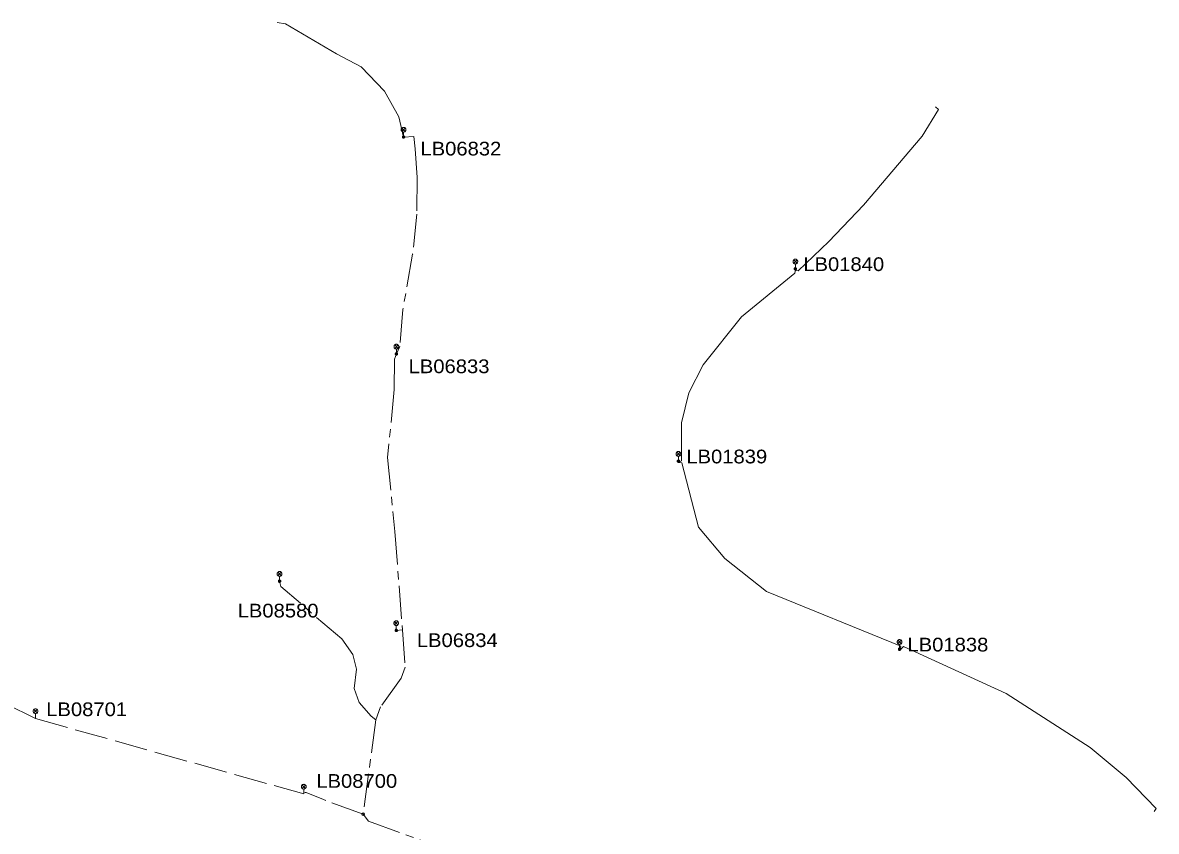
# Model space of a CAD drawing. Extents: x -686371 to -686009, y -974088 to -973838.
# Drawn here: x -686188.2 to -686009.3, y -973965.5 to -973837.8 of the extents above; entities that cross this region are included whole.
import ezdxf

# ---------------------------------------------------------------- set-up
doc = ezdxf.new("R2010")
doc.units = 0
doc.header["$LTSCALE"] = 0.87
doc.header["$PDMODE"] = 32
doc.header["$PDSIZE"] = 0.435
doc.linetypes.add('LONG_DASH_SHORT_DASH', pattern=[9.9, 6, -1.2, 1.5, -1.2])
doc.linetypes.add('LONG_DASHED', pattern=[7.5, 6, -1.5])
doc.layers.add('1', color=7, linetype='Continuous', lineweight=13)

msp = doc.modelspace()

# ---------------------------------------------------------------- linework, layer by layer
at = {"layer": '1'}
for p, q in [((-686128.345, -973854.435), (-686127.815, -973854.965)), ((-686128.345, -973854.965), (-686127.815, -973854.435)), ((-686128.08, -973855.85), (-686128.08, -973855.075)), ((-686066.505, -973875.245), (-686065.975, -973875.775)), ((-686066.505, -973875.775), (-686065.975, -973875.245)), ((-686066.24, -973876.66), (-686066.24, -973875.885)), ((-686129.475, -973888.685), (-686128.945, -973889.215)), ((-686129.475, -973889.215), (-686128.945, -973888.685)), ((-686129.21, -973890.1), (-686129.21, -973889.325)), ((-686084.965, -973905.615), (-686084.435, -973906.145)), ((-686084.965, -973906.145), (-686084.435, -973905.615)), ((-686084.7, -973907.03), (-686084.7, -973906.255)), ((-686147.915, -973924.565), (-686147.385, -973925.095)), ((-686147.915, -973925.095), (-686147.385, -973924.565)), ((-686147.65, -973925.98), (-686147.65, -973925.205)), ((-686129.495, -973932.345), (-686128.965, -973932.875)), ((-686129.495, -973932.875), (-686128.965, -973932.345)), ((-686129.23, -973933.76), (-686129.23, -973932.985)), ((-686050.065, -973935.315), (-686049.535, -973935.845)), ((-686050.065, -973935.845), (-686049.535, -973935.315)), ((-686049.8, -973936.73), (-686049.8, -973935.955)), ((-686186.425, -973946.245), (-686185.895, -973946.775)), ((-686186.425, -973946.775), (-686185.895, -973946.245)), ((-686186.16, -973947.66), (-686186.16, -973946.885)), ((-686144.085, -973958.165), (-686143.555, -973958.695)), ((-686144.085, -973958.695), (-686143.555, -973958.165)), ((-686143.82, -973959.58), (-686143.82, -973958.805))]:
    msp.add_line(p, q, dxfattribs=at)
at = {"layer": '1', "linetype": 'LONG_DASH_SHORT_DASH'}
for p, q in [((-686129.45, -973918.15), (-686128.26, -973933.66)), ((-686147.47, -973926.8), (-686147.65, -973925.98)), ((-686128.26, -973933.66), (-686129.23, -973933.76)), ((-686132.43, -973947.89), (-686134.47, -973962.76))]:
    msp.add_line(p, q, dxfattribs=at)
at = {"layer": '1', "linetype": 'LONG_DASHED'}
for q in [(-686211.97, -973935.089), (-686143.82, -973959.58)]:
    msp.add_line((-686186.16, -973947.66), q, dxfattribs=at)
at = {"layer": '1'}
for points in [[(-686148, -973837.79), (-686146.706, -973837.955), (-686138.636, -973842.736), (-686134.764, -973844.768), (-686131.105, -973848.588), (-686128.833, -973852.64), (-686128.08, -973855.85)], [(-686066.24, -973876.85), (-686065.828, -973876.979), (-686060.945, -973872.351), (-686055.499, -973866.609), (-686046.253, -973855.711), (-686043.665, -973851.493), (-686044.13, -973851.1)], [(-686084.7, -973907.22), (-686084.224, -973906.978), (-686084.224, -973901.001), (-686083.04, -973896.221), (-686080.791, -973891.806), (-686074.769, -973884.239), (-686066.31, -973877.367), (-686066.24, -973876.85)], [(-686049.8, -973936.92), (-686049.591, -973936.237), (-686070.819, -973927.615), (-686077.37, -973922.407), (-686081.535, -973917.438), (-686084.168, -973907.28), (-686084.7, -973907.22)], [(-686009.61, -973962.37), (-686009.281, -973961.862), (-686014.053, -973956.992), (-686019.73, -973952.267), (-686032.954, -973943.714), (-686049.205, -973936.292), (-686049.8, -973936.92)]]:
    msp.add_lwpolyline(points, dxfattribs=at)
for points in [[(-686127.705, -973854.7), (-686127.711, -973854.635), (-686127.728, -973854.572), (-686127.755, -973854.513), (-686127.793, -973854.459), (-686127.839, -973854.413), (-686127.892, -973854.375), (-686127.952, -973854.348), (-686128.015, -973854.331), (-686128.08, -973854.325), (-686128.145, -973854.331), (-686128.208, -973854.348), (-686128.268, -973854.375), (-686128.321, -973854.413), (-686128.367, -973854.459), (-686128.405, -973854.513), (-686128.432, -973854.572), (-686128.449, -973854.635), (-686128.455, -973854.7), (-686128.449, -973854.765), (-686128.432, -973854.828), (-686128.405, -973854.888), (-686128.367, -973854.941), (-686128.321, -973854.987), (-686128.268, -973855.025), (-686128.208, -973855.052), (-686128.145, -973855.069), (-686128.08, -973855.075), (-686128.015, -973855.069), (-686127.952, -973855.052), (-686127.892, -973855.025), (-686127.839, -973854.987), (-686127.793, -973854.941), (-686127.755, -973854.888), (-686127.728, -973854.828), (-686127.711, -973854.765)], [(-686127.89, -973855.85), (-686127.893, -973855.817), (-686127.901, -973855.785), (-686127.915, -973855.755), (-686127.934, -973855.728), (-686127.958, -973855.704), (-686127.985, -973855.685), (-686128.015, -973855.671), (-686128.047, -973855.663), (-686128.08, -973855.66), (-686128.113, -973855.663), (-686128.145, -973855.671), (-686128.175, -973855.685), (-686128.202, -973855.704), (-686128.226, -973855.728), (-686128.245, -973855.755), (-686128.259, -973855.785), (-686128.267, -973855.817), (-686128.27, -973855.85), (-686128.267, -973855.883), (-686128.259, -973855.915), (-686128.245, -973855.945), (-686128.226, -973855.972), (-686128.202, -973855.996), (-686128.175, -973856.015), (-686128.145, -973856.029), (-686128.113, -973856.037), (-686128.08, -973856.04), (-686128.047, -973856.037), (-686128.015, -973856.029), (-686127.985, -973856.015), (-686127.958, -973855.996), (-686127.934, -973855.972), (-686127.915, -973855.945), (-686127.901, -973855.915), (-686127.893, -973855.883)], [(-686128.03, -973855.85), (-686128.031, -973855.841), (-686128.033, -973855.833), (-686128.037, -973855.825), (-686128.042, -973855.818), (-686128.048, -973855.812), (-686128.055, -973855.807), (-686128.063, -973855.803), (-686128.071, -973855.801), (-686128.08, -973855.8), (-686128.089, -973855.801), (-686128.097, -973855.803), (-686128.105, -973855.807), (-686128.112, -973855.812), (-686128.118, -973855.818), (-686128.123, -973855.825), (-686128.127, -973855.833), (-686128.129, -973855.841), (-686128.13, -973855.85), (-686128.129, -973855.859), (-686128.127, -973855.867), (-686128.123, -973855.875), (-686128.118, -973855.882), (-686128.112, -973855.888), (-686128.105, -973855.893), (-686128.097, -973855.897), (-686128.089, -973855.899), (-686128.08, -973855.9), (-686128.071, -973855.899), (-686128.063, -973855.897), (-686128.055, -973855.893), (-686128.048, -973855.888), (-686128.042, -973855.882), (-686128.037, -973855.875), (-686128.033, -973855.867), (-686128.031, -973855.859)], [(-686065.865, -973875.51), (-686065.871, -973875.445), (-686065.888, -973875.382), (-686065.915, -973875.322), (-686065.953, -973875.269), (-686065.999, -973875.223), (-686066.052, -973875.185), (-686066.112, -973875.158), (-686066.175, -973875.141), (-686066.24, -973875.135), (-686066.305, -973875.141), (-686066.368, -973875.158), (-686066.428, -973875.185), (-686066.481, -973875.223), (-686066.527, -973875.269), (-686066.565, -973875.322), (-686066.592, -973875.382), (-686066.609, -973875.445), (-686066.615, -973875.51), (-686066.609, -973875.575), (-686066.592, -973875.638), (-686066.565, -973875.698), (-686066.527, -973875.751), (-686066.481, -973875.797), (-686066.428, -973875.835), (-686066.368, -973875.862), (-686066.305, -973875.879), (-686066.24, -973875.885), (-686066.175, -973875.879), (-686066.112, -973875.862), (-686066.052, -973875.835), (-686065.999, -973875.797), (-686065.953, -973875.751), (-686065.915, -973875.698), (-686065.888, -973875.638), (-686065.871, -973875.575)], [(-686066.05, -973876.66), (-686066.053, -973876.627), (-686066.061, -973876.595), (-686066.075, -973876.565), (-686066.094, -973876.538), (-686066.118, -973876.514), (-686066.145, -973876.495), (-686066.175, -973876.481), (-686066.207, -973876.473), (-686066.24, -973876.47), (-686066.273, -973876.473), (-686066.305, -973876.481), (-686066.335, -973876.495), (-686066.362, -973876.514), (-686066.386, -973876.538), (-686066.405, -973876.565), (-686066.419, -973876.595), (-686066.427, -973876.627), (-686066.43, -973876.66), (-686066.427, -973876.693), (-686066.419, -973876.725), (-686066.405, -973876.755), (-686066.386, -973876.782), (-686066.362, -973876.806), (-686066.335, -973876.825), (-686066.305, -973876.839), (-686066.273, -973876.847), (-686066.24, -973876.85), (-686066.207, -973876.847), (-686066.175, -973876.839), (-686066.145, -973876.825), (-686066.118, -973876.806), (-686066.094, -973876.782), (-686066.075, -973876.755), (-686066.061, -973876.725), (-686066.053, -973876.693)], [(-686066.19, -973876.66), (-686066.191, -973876.651), (-686066.193, -973876.643), (-686066.197, -973876.635), (-686066.202, -973876.628), (-686066.208, -973876.622), (-686066.215, -973876.617), (-686066.223, -973876.613), (-686066.231, -973876.611), (-686066.24, -973876.61), (-686066.249, -973876.611), (-686066.257, -973876.613), (-686066.265, -973876.617), (-686066.272, -973876.622), (-686066.278, -973876.628), (-686066.283, -973876.635), (-686066.287, -973876.643), (-686066.289, -973876.651), (-686066.29, -973876.66), (-686066.289, -973876.669), (-686066.287, -973876.677), (-686066.283, -973876.685), (-686066.278, -973876.692), (-686066.272, -973876.698), (-686066.265, -973876.703), (-686066.257, -973876.707), (-686066.249, -973876.709), (-686066.24, -973876.71), (-686066.231, -973876.709), (-686066.223, -973876.707), (-686066.215, -973876.703), (-686066.208, -973876.698), (-686066.202, -973876.692), (-686066.197, -973876.685), (-686066.193, -973876.677), (-686066.191, -973876.669)], [(-686128.835, -973888.95), (-686128.841, -973888.885), (-686128.858, -973888.822), (-686128.885, -973888.763), (-686128.923, -973888.709), (-686128.969, -973888.663), (-686129.022, -973888.625), (-686129.082, -973888.598), (-686129.145, -973888.581), (-686129.21, -973888.575), (-686129.275, -973888.581), (-686129.338, -973888.598), (-686129.398, -973888.625), (-686129.451, -973888.663), (-686129.497, -973888.709), (-686129.535, -973888.763), (-686129.562, -973888.822), (-686129.579, -973888.885), (-686129.585, -973888.95), (-686129.579, -973889.015), (-686129.562, -973889.078), (-686129.535, -973889.138), (-686129.497, -973889.191), (-686129.451, -973889.237), (-686129.398, -973889.275), (-686129.338, -973889.302), (-686129.275, -973889.319), (-686129.21, -973889.325), (-686129.145, -973889.319), (-686129.082, -973889.302), (-686129.022, -973889.275), (-686128.969, -973889.237), (-686128.923, -973889.191), (-686128.885, -973889.138), (-686128.858, -973889.078), (-686128.841, -973889.015)], [(-686129.02, -973890.1), (-686129.023, -973890.067), (-686129.031, -973890.035), (-686129.045, -973890.005), (-686129.064, -973889.978), (-686129.088, -973889.954), (-686129.115, -973889.935), (-686129.145, -973889.921), (-686129.177, -973889.913), (-686129.21, -973889.91), (-686129.243, -973889.913), (-686129.275, -973889.921), (-686129.305, -973889.935), (-686129.332, -973889.954), (-686129.356, -973889.978), (-686129.375, -973890.005), (-686129.389, -973890.035), (-686129.397, -973890.067), (-686129.4, -973890.1), (-686129.397, -973890.133), (-686129.389, -973890.165), (-686129.375, -973890.195), (-686129.356, -973890.222), (-686129.332, -973890.246), (-686129.305, -973890.265), (-686129.275, -973890.279), (-686129.243, -973890.287), (-686129.21, -973890.29), (-686129.177, -973890.287), (-686129.145, -973890.279), (-686129.115, -973890.265), (-686129.088, -973890.246), (-686129.064, -973890.222), (-686129.045, -973890.195), (-686129.031, -973890.165), (-686129.023, -973890.133)], [(-686129.16, -973890.1), (-686129.161, -973890.091), (-686129.163, -973890.083), (-686129.167, -973890.075), (-686129.172, -973890.068), (-686129.178, -973890.062), (-686129.185, -973890.057), (-686129.193, -973890.053), (-686129.201, -973890.051), (-686129.21, -973890.05), (-686129.219, -973890.051), (-686129.227, -973890.053), (-686129.235, -973890.057), (-686129.242, -973890.062), (-686129.248, -973890.068), (-686129.253, -973890.075), (-686129.257, -973890.083), (-686129.259, -973890.091), (-686129.26, -973890.1), (-686129.259, -973890.109), (-686129.257, -973890.117), (-686129.253, -973890.125), (-686129.248, -973890.132), (-686129.242, -973890.138), (-686129.235, -973890.143), (-686129.227, -973890.147), (-686129.219, -973890.149), (-686129.21, -973890.15), (-686129.201, -973890.149), (-686129.193, -973890.147), (-686129.185, -973890.143), (-686129.178, -973890.138), (-686129.172, -973890.132), (-686129.167, -973890.125), (-686129.163, -973890.117), (-686129.161, -973890.109)], [(-686084.325, -973905.88), (-686084.331, -973905.815), (-686084.348, -973905.752), (-686084.375, -973905.692), (-686084.413, -973905.639), (-686084.459, -973905.593), (-686084.513, -973905.555), (-686084.572, -973905.528), (-686084.635, -973905.511), (-686084.7, -973905.505), (-686084.765, -973905.511), (-686084.828, -973905.528), (-686084.888, -973905.555), (-686084.941, -973905.593), (-686084.987, -973905.639), (-686085.025, -973905.692), (-686085.052, -973905.752), (-686085.069, -973905.815), (-686085.075, -973905.88), (-686085.069, -973905.945), (-686085.052, -973906.008), (-686085.025, -973906.068), (-686084.987, -973906.121), (-686084.941, -973906.167), (-686084.888, -973906.205), (-686084.828, -973906.232), (-686084.765, -973906.249), (-686084.7, -973906.255), (-686084.635, -973906.249), (-686084.572, -973906.232), (-686084.513, -973906.205), (-686084.459, -973906.167), (-686084.413, -973906.121), (-686084.375, -973906.068), (-686084.348, -973906.008), (-686084.331, -973905.945)], [(-686084.51, -973907.03), (-686084.513, -973906.997), (-686084.521, -973906.965), (-686084.535, -973906.935), (-686084.554, -973906.908), (-686084.578, -973906.884), (-686084.605, -973906.865), (-686084.635, -973906.851), (-686084.667, -973906.843), (-686084.7, -973906.84), (-686084.733, -973906.843), (-686084.765, -973906.851), (-686084.795, -973906.865), (-686084.822, -973906.884), (-686084.846, -973906.908), (-686084.865, -973906.935), (-686084.879, -973906.965), (-686084.887, -973906.997), (-686084.89, -973907.03), (-686084.887, -973907.063), (-686084.879, -973907.095), (-686084.865, -973907.125), (-686084.846, -973907.152), (-686084.822, -973907.176), (-686084.795, -973907.195), (-686084.765, -973907.209), (-686084.733, -973907.217), (-686084.7, -973907.22), (-686084.667, -973907.217), (-686084.635, -973907.209), (-686084.605, -973907.195), (-686084.578, -973907.176), (-686084.554, -973907.152), (-686084.535, -973907.125), (-686084.521, -973907.095), (-686084.513, -973907.063)], [(-686084.65, -973907.03), (-686084.651, -973907.021), (-686084.653, -973907.013), (-686084.657, -973907.005), (-686084.662, -973906.998), (-686084.668, -973906.992), (-686084.675, -973906.987), (-686084.683, -973906.983), (-686084.691, -973906.981), (-686084.7, -973906.98), (-686084.709, -973906.981), (-686084.717, -973906.983), (-686084.725, -973906.987), (-686084.732, -973906.992), (-686084.738, -973906.998), (-686084.743, -973907.005), (-686084.747, -973907.013), (-686084.749, -973907.021), (-686084.75, -973907.03), (-686084.749, -973907.039), (-686084.747, -973907.047), (-686084.743, -973907.055), (-686084.738, -973907.062), (-686084.732, -973907.068), (-686084.725, -973907.073), (-686084.717, -973907.077), (-686084.709, -973907.079), (-686084.7, -973907.08), (-686084.691, -973907.079), (-686084.683, -973907.077), (-686084.675, -973907.073), (-686084.668, -973907.068), (-686084.662, -973907.062), (-686084.657, -973907.055), (-686084.653, -973907.047), (-686084.651, -973907.039)], [(-686147.275, -973924.83), (-686147.281, -973924.765), (-686147.298, -973924.702), (-686147.325, -973924.643), (-686147.363, -973924.589), (-686147.409, -973924.543), (-686147.462, -973924.505), (-686147.522, -973924.478), (-686147.585, -973924.461), (-686147.65, -973924.455), (-686147.715, -973924.461), (-686147.778, -973924.478), (-686147.838, -973924.505), (-686147.891, -973924.543), (-686147.937, -973924.589), (-686147.975, -973924.643), (-686148.002, -973924.702), (-686148.019, -973924.765), (-686148.025, -973924.83), (-686148.019, -973924.895), (-686148.002, -973924.958), (-686147.975, -973925.018), (-686147.937, -973925.071), (-686147.891, -973925.117), (-686147.838, -973925.155), (-686147.778, -973925.182), (-686147.715, -973925.199), (-686147.65, -973925.205), (-686147.585, -973925.199), (-686147.522, -973925.182), (-686147.462, -973925.155), (-686147.409, -973925.117), (-686147.363, -973925.071), (-686147.325, -973925.018), (-686147.298, -973924.958), (-686147.281, -973924.895)], [(-686147.46, -973925.98), (-686147.463, -973925.947), (-686147.471, -973925.915), (-686147.485, -973925.885), (-686147.504, -973925.858), (-686147.528, -973925.834), (-686147.555, -973925.815), (-686147.585, -973925.801), (-686147.617, -973925.793), (-686147.65, -973925.79), (-686147.683, -973925.793), (-686147.715, -973925.801), (-686147.745, -973925.815), (-686147.772, -973925.834), (-686147.796, -973925.858), (-686147.815, -973925.885), (-686147.829, -973925.915), (-686147.837, -973925.947), (-686147.84, -973925.98), (-686147.837, -973926.013), (-686147.829, -973926.045), (-686147.815, -973926.075), (-686147.796, -973926.102), (-686147.772, -973926.126), (-686147.745, -973926.145), (-686147.715, -973926.159), (-686147.683, -973926.167), (-686147.65, -973926.17), (-686147.617, -973926.167), (-686147.585, -973926.159), (-686147.555, -973926.145), (-686147.528, -973926.126), (-686147.504, -973926.102), (-686147.485, -973926.075), (-686147.471, -973926.045), (-686147.463, -973926.013)], [(-686147.6, -973925.98), (-686147.601, -973925.971), (-686147.603, -973925.963), (-686147.607, -973925.955), (-686147.612, -973925.948), (-686147.618, -973925.942), (-686147.625, -973925.937), (-686147.633, -973925.933), (-686147.641, -973925.931), (-686147.65, -973925.93), (-686147.659, -973925.931), (-686147.667, -973925.933), (-686147.675, -973925.937), (-686147.682, -973925.942), (-686147.688, -973925.948), (-686147.693, -973925.955), (-686147.697, -973925.963), (-686147.699, -973925.971), (-686147.7, -973925.98), (-686147.699, -973925.989), (-686147.697, -973925.997), (-686147.693, -973926.005), (-686147.688, -973926.012), (-686147.682, -973926.018), (-686147.675, -973926.023), (-686147.667, -973926.027), (-686147.659, -973926.029), (-686147.65, -973926.03), (-686147.641, -973926.029), (-686147.633, -973926.027), (-686147.625, -973926.023), (-686147.618, -973926.018), (-686147.612, -973926.012), (-686147.607, -973926.005), (-686147.603, -973925.997), (-686147.601, -973925.989)], [(-686128.855, -973932.61), (-686128.861, -973932.545), (-686128.878, -973932.482), (-686128.905, -973932.423), (-686128.943, -973932.369), (-686128.989, -973932.323), (-686129.042, -973932.285), (-686129.102, -973932.258), (-686129.165, -973932.241), (-686129.23, -973932.235), (-686129.295, -973932.241), (-686129.358, -973932.258), (-686129.418, -973932.285), (-686129.471, -973932.323), (-686129.517, -973932.369), (-686129.555, -973932.423), (-686129.582, -973932.482), (-686129.599, -973932.545), (-686129.605, -973932.61), (-686129.599, -973932.675), (-686129.582, -973932.738), (-686129.555, -973932.798), (-686129.517, -973932.851), (-686129.471, -973932.897), (-686129.418, -973932.935), (-686129.358, -973932.962), (-686129.295, -973932.979), (-686129.23, -973932.985), (-686129.165, -973932.979), (-686129.102, -973932.962), (-686129.042, -973932.935), (-686128.989, -973932.897), (-686128.943, -973932.851), (-686128.905, -973932.798), (-686128.878, -973932.738), (-686128.861, -973932.675)], [(-686129.04, -973933.76), (-686129.043, -973933.727), (-686129.051, -973933.695), (-686129.065, -973933.665), (-686129.084, -973933.638), (-686129.108, -973933.614), (-686129.135, -973933.595), (-686129.165, -973933.581), (-686129.197, -973933.573), (-686129.23, -973933.57), (-686129.263, -973933.573), (-686129.295, -973933.581), (-686129.325, -973933.595), (-686129.352, -973933.614), (-686129.376, -973933.638), (-686129.395, -973933.665), (-686129.409, -973933.695), (-686129.417, -973933.727), (-686129.42, -973933.76), (-686129.417, -973933.793), (-686129.409, -973933.825), (-686129.395, -973933.855), (-686129.376, -973933.882), (-686129.352, -973933.906), (-686129.325, -973933.925), (-686129.295, -973933.939), (-686129.263, -973933.947), (-686129.23, -973933.95), (-686129.197, -973933.947), (-686129.165, -973933.939), (-686129.135, -973933.925), (-686129.108, -973933.906), (-686129.084, -973933.882), (-686129.065, -973933.855), (-686129.051, -973933.825), (-686129.043, -973933.793)], [(-686129.18, -973933.76), (-686129.181, -973933.751), (-686129.183, -973933.743), (-686129.187, -973933.735), (-686129.192, -973933.728), (-686129.198, -973933.722), (-686129.205, -973933.717), (-686129.213, -973933.713), (-686129.221, -973933.711), (-686129.23, -973933.71), (-686129.239, -973933.711), (-686129.247, -973933.713), (-686129.255, -973933.717), (-686129.262, -973933.722), (-686129.268, -973933.728), (-686129.273, -973933.735), (-686129.277, -973933.743), (-686129.279, -973933.751), (-686129.28, -973933.76), (-686129.279, -973933.769), (-686129.277, -973933.777), (-686129.273, -973933.785), (-686129.268, -973933.792), (-686129.262, -973933.798), (-686129.255, -973933.803), (-686129.247, -973933.807), (-686129.239, -973933.809), (-686129.23, -973933.81), (-686129.221, -973933.809), (-686129.213, -973933.807), (-686129.205, -973933.803), (-686129.198, -973933.798), (-686129.192, -973933.792), (-686129.187, -973933.785), (-686129.183, -973933.777), (-686129.181, -973933.769)], [(-686049.425, -973935.58), (-686049.431, -973935.515), (-686049.448, -973935.452), (-686049.475, -973935.393), (-686049.513, -973935.339), (-686049.559, -973935.293), (-686049.612, -973935.255), (-686049.672, -973935.228), (-686049.735, -973935.211), (-686049.8, -973935.205), (-686049.865, -973935.211), (-686049.928, -973935.228), (-686049.988, -973935.255), (-686050.041, -973935.293), (-686050.087, -973935.339), (-686050.125, -973935.393), (-686050.152, -973935.452), (-686050.169, -973935.515), (-686050.175, -973935.58), (-686050.169, -973935.645), (-686050.152, -973935.708), (-686050.125, -973935.768), (-686050.087, -973935.821), (-686050.041, -973935.867), (-686049.988, -973935.905), (-686049.928, -973935.932), (-686049.865, -973935.949), (-686049.8, -973935.955), (-686049.735, -973935.949), (-686049.672, -973935.932), (-686049.612, -973935.905), (-686049.559, -973935.867), (-686049.513, -973935.821), (-686049.475, -973935.768), (-686049.448, -973935.708), (-686049.431, -973935.645)], [(-686049.61, -973936.73), (-686049.613, -973936.697), (-686049.621, -973936.665), (-686049.635, -973936.635), (-686049.654, -973936.608), (-686049.678, -973936.584), (-686049.705, -973936.565), (-686049.735, -973936.551), (-686049.767, -973936.543), (-686049.8, -973936.54), (-686049.833, -973936.543), (-686049.865, -973936.551), (-686049.895, -973936.565), (-686049.922, -973936.584), (-686049.946, -973936.608), (-686049.965, -973936.635), (-686049.979, -973936.665), (-686049.987, -973936.697), (-686049.99, -973936.73), (-686049.987, -973936.763), (-686049.979, -973936.795), (-686049.965, -973936.825), (-686049.946, -973936.852), (-686049.922, -973936.876), (-686049.895, -973936.895), (-686049.865, -973936.909), (-686049.833, -973936.917), (-686049.8, -973936.92), (-686049.767, -973936.917), (-686049.735, -973936.909), (-686049.705, -973936.895), (-686049.678, -973936.876), (-686049.654, -973936.852), (-686049.635, -973936.825), (-686049.621, -973936.795), (-686049.613, -973936.763)], [(-686049.75, -973936.73), (-686049.751, -973936.721), (-686049.753, -973936.713), (-686049.757, -973936.705), (-686049.762, -973936.698), (-686049.768, -973936.692), (-686049.775, -973936.687), (-686049.783, -973936.683), (-686049.791, -973936.681), (-686049.8, -973936.68), (-686049.809, -973936.681), (-686049.817, -973936.683), (-686049.825, -973936.687), (-686049.832, -973936.692), (-686049.838, -973936.698), (-686049.843, -973936.705), (-686049.847, -973936.713), (-686049.849, -973936.721), (-686049.85, -973936.73), (-686049.849, -973936.739), (-686049.847, -973936.747), (-686049.843, -973936.755), (-686049.838, -973936.762), (-686049.832, -973936.768), (-686049.825, -973936.773), (-686049.817, -973936.777), (-686049.809, -973936.779), (-686049.8, -973936.78), (-686049.791, -973936.779), (-686049.783, -973936.777), (-686049.775, -973936.773), (-686049.768, -973936.768), (-686049.762, -973936.762), (-686049.757, -973936.755), (-686049.753, -973936.747), (-686049.751, -973936.739)], [(-686185.785, -973946.51), (-686185.791, -973946.445), (-686185.808, -973946.382), (-686185.835, -973946.322), (-686185.873, -973946.269), (-686185.919, -973946.223), (-686185.972, -973946.185), (-686186.032, -973946.158), (-686186.095, -973946.141), (-686186.16, -973946.135), (-686186.225, -973946.141), (-686186.288, -973946.158), (-686186.348, -973946.185), (-686186.401, -973946.223), (-686186.447, -973946.269), (-686186.485, -973946.322), (-686186.512, -973946.382), (-686186.529, -973946.445), (-686186.535, -973946.51), (-686186.529, -973946.575), (-686186.512, -973946.638), (-686186.485, -973946.698), (-686186.447, -973946.751), (-686186.401, -973946.797), (-686186.348, -973946.835), (-686186.288, -973946.862), (-686186.225, -973946.879), (-686186.16, -973946.885), (-686186.095, -973946.879), (-686186.032, -973946.862), (-686185.972, -973946.835), (-686185.919, -973946.797), (-686185.873, -973946.751), (-686185.835, -973946.698), (-686185.808, -973946.638), (-686185.791, -973946.575)], [(-686143.445, -973958.43), (-686143.451, -973958.365), (-686143.468, -973958.302), (-686143.495, -973958.242), (-686143.533, -973958.189), (-686143.579, -973958.143), (-686143.633, -973958.105), (-686143.692, -973958.078), (-686143.755, -973958.061), (-686143.82, -973958.055), (-686143.885, -973958.061), (-686143.948, -973958.078), (-686144.008, -973958.105), (-686144.061, -973958.143), (-686144.107, -973958.189), (-686144.145, -973958.242), (-686144.172, -973958.302), (-686144.189, -973958.365), (-686144.195, -973958.43), (-686144.189, -973958.495), (-686144.172, -973958.558), (-686144.145, -973958.617), (-686144.107, -973958.671), (-686144.061, -973958.717), (-686144.008, -973958.755), (-686143.948, -973958.782), (-686143.885, -973958.799), (-686143.82, -973958.805), (-686143.755, -973958.799), (-686143.692, -973958.782), (-686143.633, -973958.755), (-686143.579, -973958.717), (-686143.533, -973958.671), (-686143.495, -973958.617), (-686143.468, -973958.558), (-686143.451, -973958.495)]]:
    msp.add_lwpolyline(points, close=True, dxfattribs=at)
at = {"layer": '1', "linetype": 'LONG_DASH_SHORT_DASH'}
for points in [[(-686128.08, -973855.85), (-686126.47, -973855.74), (-686126.24, -973857.71), (-686125.95, -973862.26), (-686125.96, -973868.04), (-686126.65, -973874.37), (-686128.18, -973883.1)], [(-686128.18, -973883.1), (-686128.66, -973888.91), (-686129.21, -973890.1), (-686129.49, -973890.95), (-686129.54, -973895.72), (-686130.6, -973906.43), (-686129.45, -973918.15)], [(-686128.26, -973933.66), (-686127.81, -973939.54), (-686128.43, -973941.32), (-686131.71, -973945.82), (-686132.43, -973947.89), (-686133.2, -973947.32), (-686135.1, -973945.16), (-686135.85, -973942.94), (-686135.51, -973939.86), (-686136.08, -973937.58), (-686137.84, -973935.1), (-686147.47, -973926.8)], [(-686134.47, -973962.76), (-686140.73, -973960.47), (-686143.46, -973959.34), (-686143.68, -973959.35)], [(-686134.47, -973962.76), (-686133.63, -973963.89), (-686121.76, -973968.2)]]:
    msp.add_lwpolyline(points, dxfattribs=at)
at = {"layer": '1'}
msp.add_point((-686134.47, -973962.76), dxfattribs=at)

# ---------------------------------------------------------------- texts
at = {"layer": '1', "width": 1.1}
for s, p in [('LB06832', (-686125.417, -973858.762)), ('LB01840', (-686064.994, -973877.01)), ('LB06833', (-686127.282, -973893.136)), ('LB01839', (-686083.454, -973907.38)), ('LB08580', (-686154.262, -973931.714)), ('LB06834', (-686125.981, -973936.383)), ('LB01838', (-686048.554, -973937.08)), ('LB08701', (-686184.467, -973947.291)), ('LB08700', (-686141.847, -973958.611))]:
    msp.add_text(s, height=2.167, dxfattribs=at).set_placement(p)

doc.saveas('drawing.dxf')
